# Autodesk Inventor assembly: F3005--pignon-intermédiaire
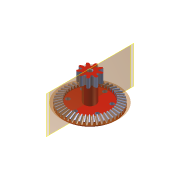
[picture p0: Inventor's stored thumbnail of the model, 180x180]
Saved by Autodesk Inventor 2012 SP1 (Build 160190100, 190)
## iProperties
Created: 2014-12
Part Number: F3005--pignon-intermédiaire
Document SubType Name: Assembly
Designer: Bruno
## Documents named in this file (3)
- D:\Cours\Systèmes\secateur-hydrogene-Pragma\Documentation\Dossier technique Infaco F3005\Solidworks\Composants importés\F3005--pignon-intermédiaire.iam
- D:\Cours\Systèmes\secateur-hydrogene-Pragma\Documentation\Dossier technique Infaco F3005\Solidworks\Composants importés\F3005\Couronne.ipt
- D:\Cours\Systèmes\secateur-hydrogene-Pragma\Documentation\Dossier technique Infaco F3005\Solidworks\Composants importés\F3005\Pignon 9dts.ipt
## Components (2 placed, 2 different names)
1. Couronne:1 — Affleurement:1
2. Pignon 9dts:1
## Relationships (1: Flush 1)
- Affleurement:1 [Flush]: Couronne:1
